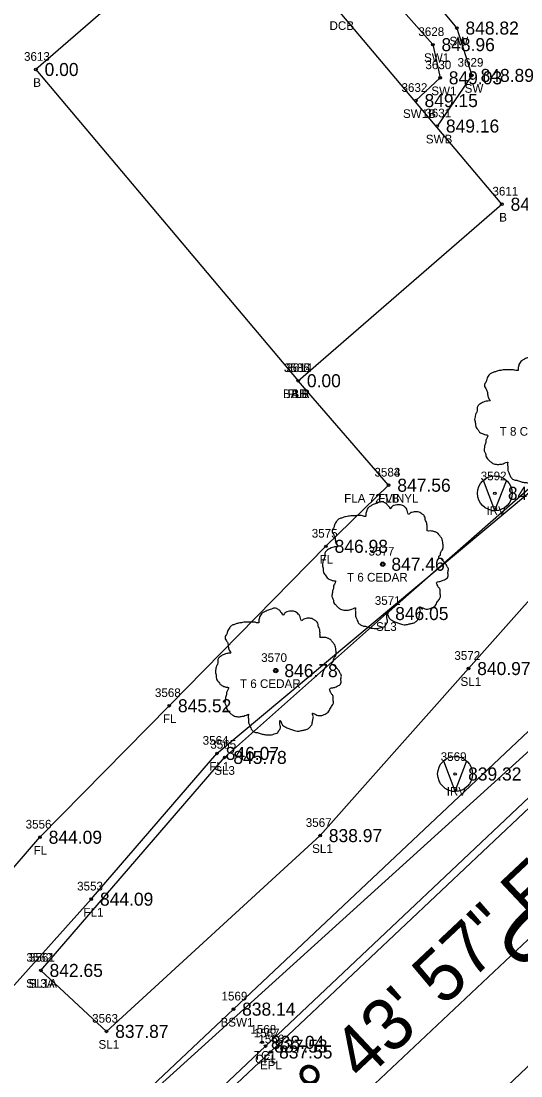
# Model space of a CAD drawing. Extents: x 1622501 to 1626664, y 1117816 to 1121579.
# Drawn here: x 1624729.6 to 1624787.1, y 1119992.2 to 1120113.7 of the extents above; entities that cross this region are included whole.
import ezdxf

# ---------------------------------------------------------------- set-up
doc = ezdxf.new("R2010")
doc.units = 0
for name, color, linetype in [('RD_EX_Bldg', 7, 'Continuous'), ('RD_EX_Bldg_txCode', 7, 'Continuous'), ('RD_EX_BldgApp', 7, 'Continuous'), ('RD_EX_Conc', 7, 'Continuous'), ('RD_EX_Conc_txCode', 7, 'Continuous'), ('RD_EX_DR_Pipe', 7, 'Continuous'), ('RD_EX_Fence_Other', 7, 'Continuous'), ('RD_EX_Fence_Other_txCode', 7, 'Continuous'), ('RD_EX_Misc_txCode', 7, 'Continuous'), ('RD_EX_Road', 7, 'Continuous'), ('RD_EX_Road_txCode', 7, 'Continuous'), ('RD_EX_TX_Bldg_ELEV', 7, 'Continuous'), ('RD_EX_TX_Conc_ELEV', 7, 'Continuous'), ('RD_EX_TX_Fence_Other_ELEV', 7, 'Continuous'), ('RD_EX_TX_Misc_ELEV', 7, 'Continuous'), ('RD_EX_TX_Road_ELEV', 7, 'Continuous'), ('RD_EX_TX_VEG_ELEV', 7, 'Continuous'), ('RD_EX_VEG', 7, 'Continuous'), ('RD_EX_VEG_txCode', 7, 'Continuous'), ('RD_HC_Cl', 7, 'Continuous'), ('RD_HC_Data', 7, 'Continuous'), ('RD_HC_TX_Sta50', 7, 'Continuous'), ('RD_SMD_Locator', 7, 'Continuous')]:
    doc.layers.add(name, color=color, linetype=linetype)

msp = doc.modelspace()

# ---------------------------------------------------------------- linework, layer by layer
at = {"layer": 'RD_EX_Bldg'}
msp.add_lwpolyline([(1624761.47, 1120072.27), (1624784.9, 1120092.59), (1624754.73, 1120128.42), (1624731.3, 1120108.1), (1624761.47, 1120072.27)], dxfattribs=at)
at = {"layer": 'RD_EX_BldgApp'}
for p, q in [((1624784.09, 1120057.32), (1624782.79, 1120060.8)), ((1624784.09, 1120057.32), (1624785.42, 1120060.76)), ((1624779.51, 1120025.01), (1624778.21, 1120028.49)), ((1624779.51, 1120025.01), (1624780.83, 1120028.45))]:
    msp.add_line(p, q, dxfattribs=at)
for centre, radius in [((1624784.09, 1120059.31), 2), ((1624784.09, 1120059.31), 0.15), ((1624779.51, 1120027), 2), ((1624779.51, 1120027), 0.15)]:
    msp.add_circle(centre, radius, dxfattribs=at)
at = {"layer": 'RD_EX_Conc'}
for points in [[(1624773.37, 1120120.54), (1624779.71, 1120112.87), (1624781.45, 1120107.42), (1624777.46, 1120101.59)], [(1624770.55, 1120118.24), (1624776.95, 1120110.96), (1624777.79, 1120107.14), (1624775, 1120104.52)], [(1624627.29, 1119872.79), (1624648.82, 1119893.33), (1624685.14, 1119927.24), (1624721.63, 1119961.54), (1624757.72, 1119995.68), (1624794.23, 1120030.2), (1624818.18, 1120052.72), (1624821.97, 1120057.48), (1624824.89, 1120062.27)], [(1624660.88, 1119912.17), (1624681.2, 1119931.28), (1624717.73, 1119965.71), (1624754.02, 1119999.93), (1624790.62, 1120034.43), (1624814.46, 1120056.83)]]:
    msp.add_lwpolyline(points, dxfattribs=at)
at = {"layer": 'RD_EX_DR_Pipe'}
msp.add_lwpolyline([(1625495.16, 1120700.17), (1625478.48, 1120693.94), (1625478.48, 1120693.94), (1625401.27, 1120618.61), (1625386.85, 1120595.89), (1625386.85, 1120595.89), (1625239.34, 1120454.58), (1625067.49, 1120292.51), (1624913.32, 1120147.08), (1624906.32, 1120142.58), (1624803.57, 1120043.73), (1624612.21, 1119870.34), (1624528.3, 1119793.12)], dxfattribs=at)
at = {"layer": 'RD_EX_Fence_Other'}
for points in [[(1624679.11, 1119949.86), (1624705.84, 1119977.07), (1624737.67, 1120012.59), (1624752.13, 1120029.37), (1624792.98, 1120063.53), (1624804.63, 1120073.99)], [(1624641.35, 1120014.22), (1624648.5, 1119999.9), (1624664.64, 1119971.73), (1624674.9, 1119954.09), (1624700.33, 1119983.2), (1624731.77, 1120019.72), (1624746.64, 1120034.86), (1624764.66, 1120053.21), (1624771.87, 1120060.24), (1624771.87, 1120060.24), (1624761.47, 1120072.27)]]:
    msp.add_lwpolyline(points, dxfattribs=at)
at = {"layer": 'RD_EX_Road'}
for points in [[(1624481.69, 1119706.57), (1624518.07, 1119740.62), (1624554.52, 1119774.63), (1624590.99, 1119808.78), (1624627.13, 1119843.17), (1624664.12, 1119876.78), (1624700.28, 1119911.28), (1624736.97, 1119945.68), (1624773.63, 1119979.8), (1624810.11, 1120014.45), (1624846.42, 1120048.91), (1624882.77, 1120083.19), (1624919.14, 1120117.14), (1624955.41, 1120151.75), (1624991.66, 1120186.11), (1625027.75, 1120220.09), (1625065.42, 1120252.96), (1625104.19, 1120284.12), (1625143.2, 1120315.04), (1625181.69, 1120345.9), (1625220.31, 1120377.13)], [(1624468.78, 1119721.97), (1624504.42, 1119755.42), (1624540.92, 1119789.52), (1624577, 1119823.63), (1624614.11, 1119858.36), (1624622.03, 1119866.66), (1624623.94, 1119868.41), (1624624.9, 1119868.05), (1624628.91, 1119871.9), (1624628.36, 1119872.68), (1624649.22, 1119892.43), (1624685.62, 1119926.57), (1624722.14, 1119961.01), (1624758.27, 1119995), (1624794.85, 1120029.55), (1624818.75, 1120051.93), (1624828.77, 1120068.77), (1624829.58, 1120080.91), (1624828.33, 1120088.31), (1624824.85, 1120095.34), (1624817.99, 1120105.91), (1624780.84, 1120159.39), (1624775.47, 1120165.89), (1624755.05, 1120187.38)]]:
    msp.add_lwpolyline(points, dxfattribs=at)
at = {"layer": 'RD_EX_VEG'}
for points in [[(1624731.87, 1120004.39), (1624739.42, 1119997.37), (1624763.99, 1120019.91), (1624781.06, 1120039.14), (1624793.96, 1120053.67), (1624790.84, 1120062.36)], [(1624731.87, 1120004.39), (1624753.01, 1120028.91), (1624771.62, 1120045.47), (1624790.84, 1120062.36)]]:
    msp.add_lwpolyline(points, dxfattribs=at)
for centre, radius in [((1624771.19, 1120051.15), 0.25), ((1624771.18, 1120051.13), 0.0001), ((1624758.88, 1120038.9), 0.25), ((1624758.86, 1120038.88), 0.0001)]:
    msp.add_circle(centre, radius, dxfattribs=at)
for points in [[(1624788.83, 1120075.11), (1624788.53, 1120075.13), (1624788.21, 1120075.03), (1624787.96, 1120074.93), (1624787.74, 1120074.86), (1624787.51, 1120074.76), (1624787.21, 1120074.58), (1624786.99, 1120074.38), (1624786.86, 1120074.13), (1624786.81, 1120073.91), (1624786.76, 1120073.63), (1624786.76, 1120073.46), (1624786.64, 1120073.43), (1624786.49, 1120073.46), (1624786.24, 1120073.53), (1624785.99, 1120073.53), (1624785.74, 1120073.53), (1624785.39, 1120073.51), (1624785.04, 1120073.51), (1624784.76, 1120073.46), (1624784.44, 1120073.41), (1624784.06, 1120073.28), (1624783.71, 1120073.16), (1624783.41, 1120072.91), (1624783.16, 1120072.43), (1624783.04, 1120072.08), (1624782.89, 1120071.83), (1624783.04, 1120071.38), (1624783.21, 1120071.03), (1624783.24, 1120070.83), (1624783.31, 1120070.41), (1624783.41, 1120070.18), (1624783.54, 1120069.98), (1624783.46, 1120069.96), (1624783.09, 1120069.91), (1624782.79, 1120069.81), (1624782.36, 1120069.58), (1624782.14, 1120069.36), (1624782.04, 1120069.03), (1624782.01, 1120068.68), (1624781.91, 1120068.48), (1624781.84, 1120068.21), (1624781.81, 1120068.13), (1624781.76, 1120067.81), (1624781.86, 1120067.36), (1624781.89, 1120067.01), (1624782.01, 1120066.78), (1624782.16, 1120066.61), (1624782.34, 1120066.36), (1624782.74, 1120066.14), (1624783.06, 1120066.04), (1624783.26, 1120066.01), (1624783.09, 1120065.51), (1624783.04, 1120065.16), (1624782.91, 1120064.76), (1624782.91, 1120064.69), (1624782.86, 1120064.21), (1624783.01, 1120063.89), (1624783.09, 1120063.51), (1624783.26, 1120063.29), (1624783.54, 1120062.99), (1624783.86, 1120062.76), (1624784.36, 1120062.64), (1624784.76, 1120062.66), (1624785.34, 1120062.84), (1624785.59, 1120062.91), (1624785.56, 1120062.74), (1624785.59, 1120062.36), (1624785.59, 1120061.94), (1624785.74, 1120061.61), (1624785.84, 1120061.34), (1624785.99, 1120061.09), (1624786.31, 1120060.86), (1624786.71, 1120060.79), (1624787.14, 1120060.64), (1624787.59, 1120060.56), (1624788.09, 1120060.54), (1624788.68, 1120060.69), (1624788.96, 1120060.81), (1624789.06, 1120060.99), (1624789.26, 1120061.36), (1624789.21, 1120061.59), (1624789.23, 1120062.19), (1624789.33, 1120062.01), (1624789.51, 1120061.66), (1624790.01, 1120061.36), (1624790.41, 1120061.19), (1624790.88, 1120061.04), (1624791.18, 1120060.96), (1624791.66, 1120061.04), (1624792.03, 1120061.11), (1624792.41, 1120061.24), (1624792.71, 1120061.51), (1624792.88, 1120061.79), (1624792.93, 1120062.06), (1624793.01, 1120062.44), (1624793.06, 1120062.61)], [(1624771.32, 1120058.32), (1624771.02, 1120058.34), (1624770.7, 1120058.24), (1624770.45, 1120058.14), (1624770.22, 1120058.07), (1624770, 1120057.97), (1624769.7, 1120057.79), (1624769.47, 1120057.59), (1624769.35, 1120057.34), (1624769.3, 1120057.12), (1624769.25, 1120056.84), (1624769.25, 1120056.67), (1624769.12, 1120056.64), (1624768.97, 1120056.67), (1624768.72, 1120056.74), (1624768.47, 1120056.74), (1624768.22, 1120056.74), (1624767.87, 1120056.72), (1624767.52, 1120056.72), (1624767.25, 1120056.67), (1624766.92, 1120056.62), (1624766.55, 1120056.49), (1624766.2, 1120056.37), (1624765.9, 1120056.12), (1624765.65, 1120055.65), (1624765.52, 1120055.3), (1624765.37, 1120055.05), (1624765.52, 1120054.6), (1624765.7, 1120054.25), (1624765.72, 1120054.05), (1624765.8, 1120053.62), (1624765.9, 1120053.4), (1624766.02, 1120053.2), (1624765.95, 1120053.17), (1624765.57, 1120053.12), (1624765.27, 1120053.02), (1624764.85, 1120052.8), (1624764.62, 1120052.57), (1624764.52, 1120052.25), (1624764.5, 1120051.9), (1624764.4, 1120051.7), (1624764.32, 1120051.42), (1624764.3, 1120051.35), (1624764.25, 1120051.02), (1624764.35, 1120050.57), (1624764.37, 1120050.22), (1624764.5, 1120050), (1624764.65, 1120049.82), (1624764.82, 1120049.57), (1624765.22, 1120049.35), (1624765.55, 1120049.25), (1624765.75, 1120049.22), (1624765.57, 1120048.72), (1624765.52, 1120048.37), (1624765.4, 1120047.97), (1624765.4, 1120047.9), (1624765.35, 1120047.42), (1624765.5, 1120047.1), (1624765.57, 1120046.72), (1624765.75, 1120046.5), (1624766.02, 1120046.2), (1624766.35, 1120045.97), (1624766.85, 1120045.85), (1624767.25, 1120045.87), (1624767.82, 1120046.05), (1624768.07, 1120046.12), (1624768.05, 1120045.95), (1624768.07, 1120045.57), (1624768.07, 1120045.15), (1624768.22, 1120044.82), (1624768.32, 1120044.55), (1624768.47, 1120044.3), (1624768.8, 1120044.08), (1624769.2, 1120044), (1624769.62, 1120043.85), (1624770.07, 1120043.78), (1624770.57, 1120043.75), (1624771.17, 1120043.9), (1624771.45, 1120044.03), (1624771.55, 1120044.2), (1624771.75, 1120044.57), (1624771.7, 1120044.8), (1624771.72, 1120045.4), (1624771.82, 1120045.22), (1624772, 1120044.87), (1624772.5, 1120044.57), (1624772.9, 1120044.4), (1624773.37, 1120044.25), (1624773.67, 1120044.18), (1624774.14, 1120044.25), (1624774.52, 1120044.33), (1624774.89, 1120044.45), (1624775.19, 1120044.72), (1624775.37, 1120045), (1624775.42, 1120045.27), (1624775.49, 1120045.65), (1624775.54, 1120045.82)], [(1624775.54, 1120045.82), (1624775.47, 1120046), (1624775.42, 1120046.25), (1624775.49, 1120046.22), (1624775.67, 1120046.17), (1624775.94, 1120046.05), (1624776.17, 1120045.97), (1624776.49, 1120046), (1624776.77, 1120046.1), (1624777.22, 1120046.37), (1624777.49, 1120046.85), (1624777.77, 1120047.25), (1624777.84, 1120047.57), (1624777.79, 1120047.8), (1624777.77, 1120048.3), (1624777.57, 1120048.55), (1624777.52, 1120048.67), (1624777.42, 1120049.07), (1624777.49, 1120049.12), (1624777.77, 1120049.17), (1624778.14, 1120049.3), (1624778.42, 1120049.42), (1624778.64, 1120049.6), (1624778.72, 1120049.82), (1624778.69, 1120050.22), (1624778.74, 1120050.62), (1624778.67, 1120050.77), (1624778.57, 1120050.92), (1624778.49, 1120051.12), (1624778.34, 1120051.27), (1624778.24, 1120051.42), (1624778.14, 1120051.52), (1624778.02, 1120051.67), (1624777.84, 1120051.8), (1624777.69, 1120051.85), (1624777.64, 1120052), (1624777.79, 1120052.2), (1624777.84, 1120052.3), (1624777.87, 1120052.52), (1624778.09, 1120052.87), (1624778.14, 1120053.27), (1624778.09, 1120053.7), (1624778.04, 1120053.97), (1624777.89, 1120054.25), (1624777.69, 1120054.5), (1624777.57, 1120054.67), (1624777.39, 1120054.8), (1624777.07, 1120054.92), (1624776.82, 1120054.97), (1624776.47, 1120054.97), (1624776.27, 1120055.02), (1624776.29, 1120055.07), (1624776.29, 1120055.22), (1624776.29, 1120055.5), (1624776.22, 1120055.94), (1624776.07, 1120056.44), (1624776.07, 1120056.47), (1624775.97, 1120056.72), (1624775.74, 1120056.92), (1624775.57, 1120057.02), (1624775.37, 1120057.14), (1624775.12, 1120057.17), (1624774.82, 1120057.17), (1624774.54, 1120057.12), (1624774.34, 1120057.02), (1624774.17, 1120056.89), (1624774.09, 1120057.04), (1624774, 1120057.34), (1624773.95, 1120057.49), (1624773.8, 1120057.67), (1624773.57, 1120057.87), (1624773.12, 1120057.99), (1624772.5, 1120057.92), (1624772.2, 1120057.72), (1624772.05, 1120057.54), (1624772, 1120057.67), (1624771.8, 1120057.87), (1624771.7, 1120058.04), (1624771.52, 1120058.17), (1624771.37, 1120058.27), (1624771.27, 1120058.32)], [(1624759.01, 1120046.06), (1624758.71, 1120046.09), (1624758.38, 1120045.99), (1624758.13, 1120045.89), (1624757.91, 1120045.81), (1624757.68, 1120045.71), (1624757.38, 1120045.54), (1624757.16, 1120045.34), (1624757.03, 1120045.09), (1624756.98, 1120044.87), (1624756.93, 1120044.59), (1624756.93, 1120044.42), (1624756.81, 1120044.39), (1624756.66, 1120044.42), (1624756.41, 1120044.49), (1624756.16, 1120044.49), (1624755.91, 1120044.49), (1624755.56, 1120044.47), (1624755.21, 1120044.47), (1624754.93, 1120044.42), (1624754.61, 1120044.37), (1624754.23, 1120044.24), (1624753.88, 1120044.12), (1624753.59, 1120043.87), (1624753.34, 1120043.39), (1624753.21, 1120043.04), (1624753.06, 1120042.79), (1624753.21, 1120042.34), (1624753.39, 1120041.99), (1624753.41, 1120041.79), (1624753.49, 1120041.37), (1624753.59, 1120041.14), (1624753.71, 1120040.94), (1624753.64, 1120040.92), (1624753.26, 1120040.87), (1624752.96, 1120040.77), (1624752.54, 1120040.54), (1624752.31, 1120040.32), (1624752.21, 1120039.99), (1624752.19, 1120039.64), (1624752.09, 1120039.44), (1624752.01, 1120039.17), (1624751.99, 1120039.09), (1624751.94, 1120038.77), (1624752.04, 1120038.32), (1624752.06, 1120037.97), (1624752.19, 1120037.74), (1624752.34, 1120037.57), (1624752.51, 1120037.32), (1624752.91, 1120037.09), (1624753.24, 1120036.99), (1624753.44, 1120036.97), (1624753.26, 1120036.47), (1624753.21, 1120036.12), (1624753.09, 1120035.72), (1624753.09, 1120035.64), (1624753.04, 1120035.17), (1624753.19, 1120034.84), (1624753.26, 1120034.47), (1624753.44, 1120034.24), (1624753.71, 1120033.94), (1624754.03, 1120033.72), (1624754.53, 1120033.59), (1624754.93, 1120033.62), (1624755.51, 1120033.79), (1624755.76, 1120033.87), (1624755.73, 1120033.69), (1624755.76, 1120033.32), (1624755.76, 1120032.9), (1624755.91, 1120032.57), (1624756.01, 1120032.3), (1624756.16, 1120032.05), (1624756.48, 1120031.82), (1624756.88, 1120031.75), (1624757.31, 1120031.6), (1624757.76, 1120031.52), (1624758.26, 1120031.5), (1624758.86, 1120031.65), (1624759.13, 1120031.77), (1624759.23, 1120031.95), (1624759.43, 1120032.32), (1624759.38, 1120032.55), (1624759.41, 1120033.15), (1624759.51, 1120032.97), (1624759.68, 1120032.62), (1624760.18, 1120032.32), (1624760.58, 1120032.15), (1624761.06, 1120032), (1624761.36, 1120031.92), (1624761.83, 1120032), (1624762.21, 1120032.07), (1624762.58, 1120032.2), (1624762.88, 1120032.47), (1624763.06, 1120032.75), (1624763.11, 1120033.02), (1624763.18, 1120033.4), (1624763.23, 1120033.57)], [(1624763.23, 1120033.57), (1624763.16, 1120033.74), (1624763.11, 1120033.99), (1624763.18, 1120033.97), (1624763.36, 1120033.92), (1624763.63, 1120033.79), (1624763.86, 1120033.72), (1624764.18, 1120033.74), (1624764.46, 1120033.84), (1624764.91, 1120034.12), (1624765.18, 1120034.59), (1624765.45, 1120034.99), (1624765.53, 1120035.32), (1624765.48, 1120035.54), (1624765.45, 1120036.04), (1624765.25, 1120036.29), (1624765.2, 1120036.42), (1624765.1, 1120036.82), (1624765.18, 1120036.87), (1624765.45, 1120036.92), (1624765.83, 1120037.04), (1624766.1, 1120037.17), (1624766.33, 1120037.34), (1624766.4, 1120037.57), (1624766.38, 1120037.97), (1624766.43, 1120038.37), (1624766.35, 1120038.52), (1624766.25, 1120038.67), (1624766.18, 1120038.87), (1624766.03, 1120039.02), (1624765.93, 1120039.17), (1624765.83, 1120039.27), (1624765.7, 1120039.42), (1624765.53, 1120039.54), (1624765.38, 1120039.59), (1624765.33, 1120039.74), (1624765.48, 1120039.94), (1624765.53, 1120040.04), (1624765.55, 1120040.27), (1624765.78, 1120040.62), (1624765.83, 1120041.02), (1624765.78, 1120041.44), (1624765.73, 1120041.72), (1624765.58, 1120041.99), (1624765.38, 1120042.24), (1624765.25, 1120042.42), (1624765.08, 1120042.54), (1624764.76, 1120042.67), (1624764.51, 1120042.72), (1624764.16, 1120042.72), (1624763.96, 1120042.77), (1624763.98, 1120042.82), (1624763.98, 1120042.97), (1624763.98, 1120043.24), (1624763.91, 1120043.69), (1624763.76, 1120044.19), (1624763.76, 1120044.22), (1624763.66, 1120044.47), (1624763.43, 1120044.67), (1624763.26, 1120044.77), (1624763.06, 1120044.89), (1624762.81, 1120044.92), (1624762.51, 1120044.92), (1624762.23, 1120044.87), (1624762.03, 1120044.77), (1624761.86, 1120044.64), (1624761.78, 1120044.79), (1624761.68, 1120045.09), (1624761.63, 1120045.24), (1624761.48, 1120045.41), (1624761.26, 1120045.61), (1624760.81, 1120045.74), (1624760.18, 1120045.66), (1624759.88, 1120045.46), (1624759.73, 1120045.29), (1624759.68, 1120045.41), (1624759.48, 1120045.61), (1624759.38, 1120045.79), (1624759.21, 1120045.91), (1624759.06, 1120046.01), (1624758.96, 1120046.06)]]:
    msp.add_spline(points, degree=3, dxfattribs=at)
at = {"layer": 'RD_HC_Cl'}
msp.add_line((1624678.65, 1119905.11), (1624870.49, 1120085.68), dxfattribs=at)
at = {"layer": 'RD_SMD_Locator'}
for centre in [(1624779.71, 1120112.87), (1624776.95, 1120110.96), (1624731.3, 1120108.1), (1624777.79, 1120107.14), (1624781.45, 1120107.42), (1624775, 1120104.52), (1624777.46, 1120101.59), (1624784.9, 1120092.59), (1624761.47, 1120072.27), (1624761.47, 1120072.27), (1624761.47, 1120072.27), (1624771.87, 1120060.24), (1624771.87, 1120060.24), (1624764.66, 1120053.21), (1624771.19, 1120051.15), (1624771.62, 1120045.47), (1624781.06, 1120039.14), (1624758.88, 1120038.9), (1624746.64, 1120034.86), (1624752.13, 1120029.37), (1624753.01, 1120028.91), (1624731.77, 1120019.72), (1624763.99, 1120019.91), (1624737.67, 1120012.59), (1624731.87, 1120004.39), (1624731.87, 1120004.39), (1624754.02, 1119999.93), (1624739.42, 1119997.37), (1624757.34, 1119996.11), (1624757.72, 1119995.68), (1624758.27, 1119995)]:
    msp.add_circle(centre, 0.15, dxfattribs=at)

# ---------------------------------------------------------------- texts
at = {"layer": 'RD_EX_Bldg_txCode'}
for s, p in [('3613', (1624729.93, 1120109.1)), ('B', (1624730.99, 1120106.1)), ('3611', (1624783.81, 1120093.59)), ('B', (1624784.59, 1120090.59)), ('3586', (1624759.82, 1120073.27)), ('3614', (1624760.1, 1120073.27)), ('BA R', (1624759.71, 1120070.27)), ('BB', (1624760.69, 1120070.27))]:
    msp.add_text(s, height=1, dxfattribs=at).set_placement(p)
at = {"layer": 'RD_EX_Conc_txCode'}
for s, p in [('DCB', (1624765.07, 1120112.65)), ('3628', (1624775.29, 1120111.96)), ('SW', (1624778.87, 1120110.87)), ('SW1', (1624775.94, 1120108.96)), ('3630', (1624776.1, 1120108.14)), ('3629', (1624779.8, 1120108.42)), ('3632', (1624773.35, 1120105.52)), ('SW1', (1624776.78, 1120105.14)), ('SW', (1624780.61, 1120105.42)), ('SW1B', (1624773.52, 1120102.52)), ('3631', (1624776.09, 1120102.59)), ('SWB', (1624776.15, 1120099.59)), ('1569', (1624752.65, 1120000.93)), ('BSW1', (1624752.54, 1119997.93)), ('1568', (1624755.97, 1119997.11)), ('1567', (1624756.35, 1119996.68)), ('TC1', (1624756.38, 1119994.11)), ('CFL', (1624756.51, 1119993.68))]:
    msp.add_text(s, height=1, dxfattribs=at).set_placement(p)
at = {"layer": 'RD_EX_Fence_Other_txCode'}
for s, p in [('3585', (1624759.84, 1120073.27)), ('FLB', (1624760.27, 1120070.27)), ('3583', (1624770.24, 1120061.24)), ('3584', (1624770.24, 1120061.24)), ('FLA 72 VINYL', (1624766.76, 1120058.24)), ('FLB', (1624770.67, 1120058.24)), ('3575', (1624763.03, 1120054.21)), ('FL', (1624763.93, 1120051.21)), ('3568', (1624744.99, 1120035.86)), ('FL', (1624745.91, 1120032.86)), ('3564', (1624750.48, 1120030.37)), ('FL1', (1624751.24, 1120027.37)), ('3556', (1624730.12, 1120020.72)), ('FL', (1624731.04, 1120017.72)), ('3553', (1624736.04, 1120013.59)), ('FL1', (1624736.77, 1120010.59))]:
    msp.add_text(s, height=1, dxfattribs=at).set_placement(p)
at = {"layer": 'RD_EX_Misc_txCode'}
for s, p in [('3592', (1624782.46, 1120060.81)), ('IRV', (1624783.13, 1120056.81)), ('3569', (1624777.86, 1120028.5)), ('IRV', (1624778.55, 1120024.5))]:
    msp.add_text(s, height=1, dxfattribs=at).set_placement(p)
at = {"layer": 'RD_EX_Road_txCode'}
for s, p in [('1566', (1624756.88, 1119996)), ('EPL', (1624757.07, 1119993))]:
    msp.add_text(s, height=1, dxfattribs=at).set_placement(p)
at = {"layer": 'RD_EX_TX_Bldg_ELEV'}
for s, p in [('0.00', (1624732.3, 1120107.35)), ('848.76', (1624785.9, 1120091.84)), ('0.00', (1624762.47, 1120071.52)), ('0.00', (1624762.47, 1120071.52))]:
    msp.add_text(s, height=1.5, dxfattribs=at).set_placement(p)
at = {"layer": 'RD_EX_TX_Conc_ELEV'}
for s, p in [('848.82', (1624780.71, 1120112.12)), ('848.96', (1624777.95, 1120110.21)), ('849.03', (1624778.79, 1120106.39)), ('848.89', (1624782.45, 1120106.67)), ('849.15', (1624776, 1120103.77)), ('849.16', (1624778.46, 1120100.84)), ('838.14', (1624755.02, 1119999.18)), ('838.04', (1624758.34, 1119995.36)), ('837.53', (1624758.72, 1119994.93))]:
    msp.add_text(s, height=1.5, dxfattribs=at).set_placement(p)
at = {"layer": 'RD_EX_TX_Fence_Other_ELEV'}
for s, p in [('0.00', (1624762.47, 1120071.52)), ('847.56', (1624772.87, 1120059.49)), ('847.56', (1624772.87, 1120059.49)), ('846.98', (1624765.66, 1120052.46)), ('845.52', (1624747.64, 1120034.11)), ('846.07', (1624753.13, 1120028.62)), ('844.09', (1624732.77, 1120018.97)), ('844.09', (1624738.67, 1120011.84))]:
    msp.add_text(s, height=1.5, dxfattribs=at).set_placement(p)
at = {"layer": 'RD_EX_TX_Misc_ELEV'}
for s, p in [('847.52', (1624785.59, 1120058.56)), ('839.32', (1624781.01, 1120026.25))]:
    msp.add_text(s, height=1.5, dxfattribs=at).set_placement(p)
at = {"layer": 'RD_EX_TX_Road_ELEV'}
msp.add_text('837.55', height=1.5, dxfattribs=at).set_placement((1624759.27, 1119994.25))
at = {"layer": 'RD_EX_TX_VEG_ELEV'}
for s, p in [('847.46', (1624772.19, 1120050.4)), ('846.05', (1624772.62, 1120044.72)), ('846.78', (1624759.88, 1120038.15)), ('840.97', (1624782.06, 1120038.39)), ('845.78', (1624754.01, 1120028.16)), ('838.97', (1624764.99, 1120019.16)), ('842.65', (1624732.87, 1120003.64)), ('842.65', (1624732.87, 1120003.64)), ('837.87', (1624740.42, 1119996.62))]:
    msp.add_text(s, height=1.5, dxfattribs=at).set_placement(p)
at = {"layer": 'RD_EX_VEG_txCode'}
for s, p in [('T 8 CEDAR', (1624784.64, 1120065.94)), ('3577', (1624769.56, 1120052.15)), ('T 6 CEDAR', (1624767.08, 1120049.15)), ('3571', (1624770.28, 1120046.47)), ('SL3', (1624770.42, 1120043.47)), ('3570', (1624757.21, 1120039.9)), ('3572', (1624779.43, 1120040.14)), ('SL1', (1624780.14, 1120037.14)), ('T 6 CEDAR', (1624754.77, 1120036.9)), ('3565', (1624751.36, 1120029.91)), ('SL3', (1624751.81, 1120026.91)), ('3567', (1624762.34, 1120020.91)), ('SL1', (1624763.07, 1120017.91)), ('3562', (1624730.21, 1120005.39)), ('3561', (1624730.5, 1120005.39)), ('SL3A', (1624730.17, 1120002.39)), ('SL1A', (1624730.46, 1120002.39)), ('3563', (1624737.77, 1119998.37)), ('SL1', (1624738.5, 1119995.37))]:
    msp.add_text(s, height=1, dxfattribs=at).set_placement(p)
at = {"layer": 'RD_HC_Data'}
msp.add_text('N 46%%d 43\' 57" E', height=6, rotation=43.2675, dxfattribs=at).set_placement((1624752.61, 1119976.1))
at = {"layer": 'RD_HC_TX_Sta50'}
msp.add_text('10', height=8, rotation=134.7975, dxfattribs=at).set_placement((1624797.94, 1120005.47))

doc.saveas('drawing.dxf')
